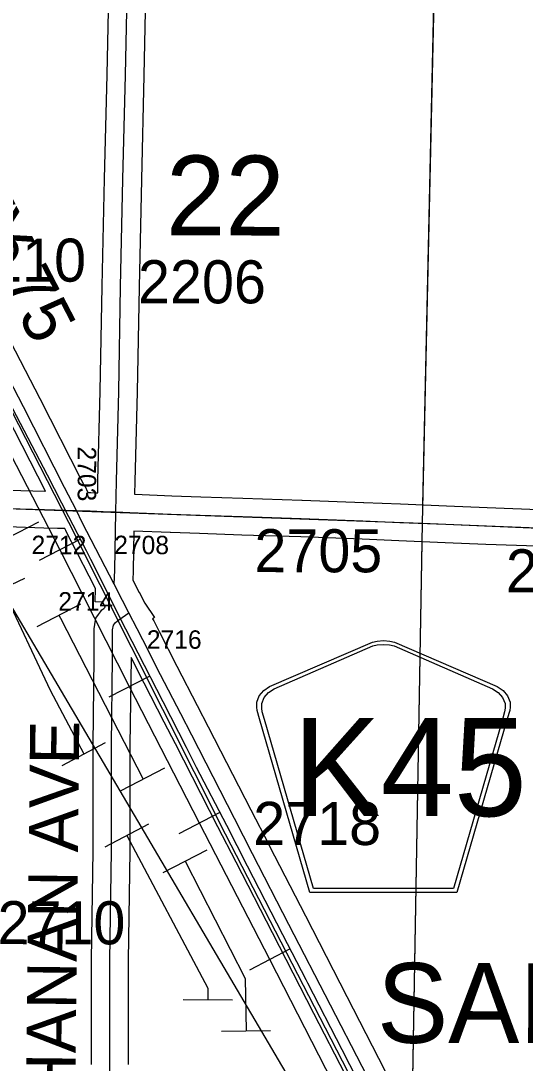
# Model space of a CAD drawing. Extents: x -157.2 to -99.3, y 12.2 to 46.2.
# Drawn here: x -143.504 to -142.682, y 24.227 to 25.924 of the extents above; entities that cross this region are included whole.
import ezdxf

# ---------------------------------------------------------------- set-up
doc = ezdxf.new("R2010")
doc.units = 0
for name, color, linetype in [('tdCoCorpTxt', 7, 'Continuous'), ('tdCoPipe', 7, 'Continuous'), ('tdCoPipe1', 7, 'Continuous'), ('tdCoPipe2', 7, 'Continuous'), ('tdCoRRCL', 7, 'Continuous'), ('tdCoSecRdNmbr', 7, 'Continuous'), ('tdCoSecRdTxt', 7, 'Continuous'), ('tdCoSecRteBand', 7, 'Continuous'), ('tdCoSecRteCL', 7, 'Continuous'), ('tdCoSectLine', 7, 'Continuous'), ('tdCoSectLinePart', 7, 'Continuous'), ('tdCoSectNmbr', 7, 'Continuous'), ('tdCoShieldCoRteHrd', 7, 'Continuous'), ('tdCoSurfAsphalt', 7, 'Continuous'), ('tdCoSurfConc', 7, 'Continuous'), ('tdCoSurfEarth', 7, 'Continuous'), ('tdCoSurfGravel', 7, 'Continuous')]:
    doc.layers.add(name, color=color, linetype=linetype)

msp = doc.modelspace()

# ---------------------------------------------------------------- linework, layer by layer
at = {"layer": 'tdCoPipe'}
msp.add_lwpolyline([(-144.5317, 38.1832), (-143.5928, 36.8918), (-143.6099, 34.8602), (-143.4402, 34.5415), (-143.5694, 34.3304), (-143.5634, 33.7239), (-143.4667, 33.4993), (-143.5656, 33.4168), (-143.4755, 33.1706), (-143.455, 32.2186), (-143.5122, 31.3968), (-143.6938, 30.9939), (-143.6811, 29.9265), (-143.7347, 27.6406), (-143.7362, 26.8708), (-143.9217, 26.7732), (-143.8183, 26.5085), (-143.8116, 26.1034), (-144.0839, 25.9289), (-143.0557, 24.1836)], dxfattribs=at)
at = {"layer": 'tdCoPipe1'}
for p, q in [((-143.5457, 25.0716), (-143.4743, 25.1082)), ((-143.4772, 24.9381), (-143.4059, 24.9747)), ((-143.3403, 24.6712), (-143.269, 24.7078)), ((-143.2718, 24.5377), (-143.2005, 24.5743)), ((-143.1771, 24.2791), (-143.0969, 24.2802))]:
    msp.add_line(p, q, dxfattribs=at)
for points in [[(-143.4415, 24.9564), (-143.439, 24.9515), (-143.3046, 24.6895)], [(-143.2362, 24.556), (-143.1381, 24.3649), (-143.137, 24.2797)]]:
    msp.add_lwpolyline(points, dxfattribs=at)
at = {"layer": 'tdCoPipe2'}
for p, q in [((-143.5698, 24.9824), (-143.4973, 25.0166)), ((-143.4363, 24.7118), (-143.3655, 24.7493)), ((-143.3662, 24.5792), (-143.2953, 24.6167)), ((-143.2393, 24.3307), (-143.1592, 24.3304))]:
    msp.add_line(p, q, dxfattribs=at)
for points in [[(-143.5336, 24.9995), (-143.4557, 24.8341), (-143.4009, 24.7305)], [(-143.3308, 24.5979), (-143.1992, 24.3491), (-143.1992, 24.3306)]]:
    msp.add_lwpolyline(points, dxfattribs=at)
at = {"layer": 'tdCoRRCL'}
for p, q in [((-143.4073, 25.0797), (-143.4739, 25.0452)), ((-143.2936, 24.8571), (-143.3604, 24.823)), ((-143.1797, 24.6354), (-143.2462, 24.6007)), ((-143.0649, 24.4131), (-143.1315, 24.3786))]:
    msp.add_line(p, q, dxfattribs=at)
for points in [[(-142.7262, 23.739), (-143.1704, 24.6), (-143.4255, 25.1074), (-144.37, 26.9512), (-144.9761, 28.127), (-145.218, 28.6071), (-145.4618, 29.0746), (-145.6726, 29.4889)], [(-142.984, 24.1736), (-143.0984, 24.3958), (-143.2126, 24.6181), (-143.3271, 24.8407), (-143.4403, 25.0634), (-143.5554, 25.2851), (-143.6701, 25.5081), (-143.7843, 25.7301), (-143.8986, 25.9522), (-144.0122, 26.1747), (-144.1269, 26.3975), (-144.241, 26.6197), (-144.3551, 26.8418), (-144.4697, 27.0637), (-144.5841, 27.286), (-144.6989, 27.509), (-144.8132, 27.7309), (-144.9272, 27.9528), (-145.0424, 28.1754), (-145.1566, 28.3975), (-145.2703, 28.62), (-145.3849, 28.8426), (-145.4992, 29.0643), (-145.6132, 29.2868)], [(-142.9429, 24.1755), (-142.9806, 24.2489), (-143.0365, 24.3577), (-143.039, 24.3626), (-143.0771, 24.4361), (-143.1345, 24.548), (-143.1683, 24.6141), (-143.2176, 24.7085), (-143.2338, 24.741), (-143.2719, 24.8152), (-143.3327, 24.9339), (-143.3898, 25.047), (-143.3969, 25.061), (-143.4255, 25.1164), (-143.4603, 25.1843), (-143.5233, 25.3046), (-143.5662, 25.3882), (-143.6239, 25.4996), (-143.6467, 25.5451), (-143.6653, 25.5824), (-143.7209, 25.6883), (-143.7702, 25.7851), (-143.8195, 25.8805), (-143.8562, 25.9518)]]:
    msp.add_lwpolyline(points, dxfattribs=at)
at = {"layer": 'tdCoSecRteBand'}
for points in [[(-143.3784, 25.1556), (-143.378, 25.1752), (-143.378, 25.1753), (-143.378, 25.1754), (-143.3743, 25.3213), (-143.3711, 25.4916), (-143.3711, 25.4916), (-143.3711, 25.4917), (-143.3674, 25.6668), (-143.3674, 25.6668), (-143.3674, 25.6669), (-143.3632, 25.8362), (-143.3593, 26.0194)], [(-143.2993, 26.0181), (-143.3032, 25.8349), (-143.3032, 25.8348), (-143.3032, 25.8348), (-143.3074, 25.6654), (-143.3111, 25.4904), (-143.3143, 25.3201), (-143.3143, 25.32), (-143.3143, 25.3199), (-143.318, 25.174), (-143.3184, 25.1533), (-143.3179, 25.1533), (-143.3179, 25.1533), (-143.2579, 25.1508), (-143.2105, 25.1491), (-143.142, 25.1469), (-143.0461, 25.1439), (-143.0459, 25.1439), (-143.0458, 25.1439), (-142.9455, 25.14), (-142.9454, 25.14), (-142.9454, 25.14), (-142.8855, 25.1375), (-142.8854, 25.1375), (-142.8854, 25.1375), (-142.8105, 25.1343), (-142.7442, 25.1316), (-142.6609, 25.1284)], [(-143.5609, 25.4789), (-143.4729, 25.3091), (-143.4728, 25.309), (-143.4728, 25.3089), (-143.406, 25.1778), (-143.4002, 25.1666), (-143.3996, 25.1669), (-143.3943, 25.1562), (-143.3899, 25.156), (-143.3897, 25.156), (-143.3897, 25.156), (-143.3823, 25.1558), (-143.3823, 25.1557), (-143.3784, 25.1556)], [(-143.4634, 25.1582), (-143.5262, 25.2815)], [(-143.5234, 25.16), (-143.4644, 25.1582), (-143.4644, 25.1582), (-143.4643, 25.1582), (-143.4634, 25.1582)], [(-143.3888, 24.2252), (-143.3886, 24.3952), (-143.3886, 24.3953), (-143.3886, 24.3955), (-143.3861, 24.5729), (-143.3859, 24.7449), (-143.3859, 24.745), (-143.3859, 24.7452), (-143.3841, 24.887), (-143.3841, 24.9325), (-143.3841, 24.935), (-143.3837, 24.9374), (-143.3825, 24.9448), (-143.3813, 24.9517), (-143.3772, 24.9574), (-143.374, 24.9619), (-143.3717, 24.9651), (-143.3687, 24.9675), (-143.3662, 24.9696), (-143.3703, 24.9775), (-143.3828, 24.978), (-143.3819, 25.0001), (-143.3921, 25.0197), (-143.4302, 25.0936), (-143.4304, 25.0938), (-143.4305, 25.094), (-143.4321, 25.0973), (-143.4441, 25.0976), (-143.4661, 25.0983), (-143.5253, 25.1)], [(-142.6633, 25.0685), (-142.7466, 25.0717), (-142.7466, 25.0717), (-142.7466, 25.0717), (-142.813, 25.0744), (-142.813, 25.0744), (-142.813, 25.0744), (-142.888, 25.0776), (-142.9478, 25.08), (-143.048, 25.084), (-143.1439, 25.0869), (-143.1439, 25.0869), (-143.1439, 25.0869), (-143.2125, 25.0892), (-143.2125, 25.0892), (-143.2126, 25.0892), (-143.2602, 25.0909), (-143.2602, 25.0909), (-143.2603, 25.0909), (-143.3195, 25.0933), (-143.3207, 25.0291), (-143.3207, 25.0287), (-143.3207, 25.0284), (-143.3213, 25.0135), (-143.3147, 25.0007), (-143.3147, 25.0007), (-143.3113, 24.994), (-143.3112, 24.9939), (-143.3019, 24.9758), (-143.2859, 24.9528), (-143.289, 24.9507), (-143.2873, 24.9473), (-143.2784, 24.9298), (-143.2494, 24.8732), (-143.2166, 24.8096), (-143.2166, 24.8096), (-143.2166, 24.8096), (-143.1986, 24.7746), (-143.1986, 24.7746), (-143.1986, 24.7745), (-143.1293, 24.6394), (-143.0995, 24.5818), (-143.0995, 24.5818), (-143.0995, 24.5817), (-143.0403, 24.4668), (-143.0403, 24.4668), (-143.0403, 24.4668), (-142.973, 24.3355), (-142.9214, 24.2356), (-142.9214, 24.2356), (-142.9214, 24.2356), (-142.8995, 24.1929)], [(-142.9748, 24.2081), (-143.0263, 24.308), (-143.0263, 24.308), (-143.0263, 24.308), (-143.0937, 24.4394), (-143.1528, 24.5542), (-143.1826, 24.6119), (-143.1827, 24.612), (-143.1827, 24.612), (-143.252, 24.7472), (-143.27, 24.7821), (-143.3028, 24.8458), (-143.3028, 24.8458), (-143.3028, 24.8458), (-143.3241, 24.8876), (-143.3241, 24.8869), (-143.3241, 24.8867), (-143.3241, 24.8865), (-143.3259, 24.7446), (-143.3261, 24.5726), (-143.3261, 24.5724), (-143.3261, 24.5723), (-143.3286, 24.3949), (-143.3288, 24.2249)]]:
    msp.add_lwpolyline(points, dxfattribs=at)
at = {"layer": 'tdCoSecRteCL'}
for points in [[(-143.349, 25.1244), (-143.348, 25.1746), (-143.3443, 25.3206), (-143.3411, 25.491), (-143.3374, 25.6661), (-143.3332, 25.8355), (-143.3293, 26.0188), (-143.3269, 26.1241)], [(-143.4132, 25.1267), (-143.4327, 25.1641), (-143.4995, 25.2953), (-143.5876, 25.4652), (-143.6455, 25.5779), (-143.6776, 25.6403), (-143.7444, 25.7702), (-143.808, 25.8925), (-143.8205, 25.917)], [(-143.8493, 25.1417), (-143.8221, 25.1408), (-143.8164, 25.1406), (-143.7407, 25.1379), (-143.6684, 25.1352), (-143.5868, 25.1325), (-143.5244, 25.13), (-143.4652, 25.1283), (-143.4132, 25.1267)], [(-143.3516, 25.0068), (-143.4036, 25.1073), (-143.4132, 25.1267)], [(-143.4132, 25.1267), (-143.3908, 25.126), (-143.3587, 25.1248), (-143.349, 25.1244)], [(-143.3516, 25.0068), (-143.3507, 25.0296), (-143.349, 25.1244)], [(-143.349, 25.1244), (-143.3264, 25.1236), (-143.2591, 25.1209), (-143.2115, 25.1191), (-143.1429, 25.1169), (-143.047, 25.114), (-142.9466, 25.11), (-142.8867, 25.1075), (-142.8117, 25.1043), (-142.7454, 25.1016), (-142.662, 25.0984), (-142.576, 25.0945), (-142.4579, 25.0893), (-142.3728, 25.0851), (-142.3539, 25.0841)], [(-143.3277, 24.9603), (-143.338, 24.9803), (-143.3516, 25.0068)], [(-143.3676, 23.6276), (-143.3667, 23.7285), (-143.3657, 23.7759), (-143.3643, 23.9056), (-143.361, 24.058), (-143.3588, 24.225), (-143.3586, 24.3951), (-143.3561, 24.5727), (-143.3559, 24.7448), (-143.3541, 24.8869), (-143.3541, 24.9325), (-143.3529, 24.9399), (-143.3497, 24.9443), (-143.3443, 24.9488), (-143.3277, 24.9603)], [(-142.8896, 24.1076), (-142.9261, 24.1792), (-142.9481, 24.2219), (-142.9996, 24.3217), (-143.067, 24.4531), (-143.1262, 24.568), (-143.156, 24.6257), (-143.2253, 24.7609), (-143.2433, 24.7959), (-143.2761, 24.8595), (-143.3051, 24.9161), (-143.3143, 24.9342), (-143.3277, 24.9603)]]:
    msp.add_lwpolyline(points, dxfattribs=at)
at = {"layer": 'tdCoSectLine'}
for points in [[(-142.8498, 25.106), (-142.8275, 26.1035)], [(-143.8497, 25.1417), (-142.8498, 25.106)], [(-142.8668, 24.1102), (-142.8498, 25.106)], [(-142.8498, 25.106), (-141.852, 25.0633)]]:
    msp.add_lwpolyline(points, dxfattribs=at)
at = {"layer": 'tdCoSectLinePart'}
for points in [[(-142.8491, 25.1359), (-142.8282, 26.0741)], [(-142.8663, 24.1401), (-142.8503, 25.076)]]:
    msp.add_lwpolyline(points, dxfattribs=at)
at = {"layer": 'tdCoShieldCoRteHrd'}
for points in [[(-143.033, 24.505), (-143.115, 24.7879), (-143.1188, 24.8011), (-143.1196, 24.8069), (-143.1196, 24.8148), (-143.1153, 24.8251), (-143.1081, 24.8336), (-143.0985, 24.8402), (-142.9312, 24.9126), (-142.9237, 24.9142), (-142.9133, 24.9151), (-142.9028, 24.9142), (-142.8953, 24.9126), (-142.728, 24.8402), (-142.7185, 24.8336), (-142.7112, 24.8251), (-142.707, 24.8148), (-142.707, 24.8069), (-142.7077, 24.8011), (-142.7116, 24.7879), (-142.7935, 24.505)], [(-143.0272, 24.5113), (-143.1069, 24.7866), (-143.1106, 24.7992), (-143.1113, 24.8049), (-143.1113, 24.8124), (-143.1072, 24.8223), (-143.1003, 24.8304), (-143.0911, 24.8368), (-142.9305, 24.9063), (-142.9233, 24.9079), (-142.9133, 24.9087), (-142.9033, 24.9079), (-142.896, 24.9063), (-142.7355, 24.8368), (-142.7263, 24.8304), (-142.7193, 24.8223), (-142.7152, 24.8124), (-142.7152, 24.8049), (-142.7159, 24.7992), (-142.7196, 24.7866), (-142.7994, 24.5113)]]:
    msp.add_lwpolyline(points, close=True, dxfattribs=at)
at = {"layer": 'tdCoSurfAsphalt'}
for points in [[(-143.3051, 24.9161), (-143.3143, 24.9342), (-143.3277, 24.9603), (-143.338, 24.9803), (-143.3516, 25.0068), (-143.4036, 25.1073), (-143.4132, 25.1267), (-143.4327, 25.1641), (-143.4995, 25.2953), (-143.5876, 25.4652), (-143.6455, 25.5779), (-143.6776, 25.6403), (-143.7444, 25.7702), (-143.808, 25.8925), (-143.8205, 25.917), (-143.8346, 25.9446)], [(-142.8896, 24.1076), (-142.9261, 24.1792), (-142.9481, 24.2219), (-142.9996, 24.3217), (-143.067, 24.4531), (-143.1262, 24.568), (-143.156, 24.6257), (-143.2253, 24.7609), (-143.2433, 24.7959), (-143.2761, 24.8595), (-143.3051, 24.9161)]]:
    msp.add_lwpolyline(points, dxfattribs=at)
at = {"layer": 'tdCoSurfConc'}
msp.add_lwpolyline([(-144.4941, 25.1459), (-144.3873, 25.1424), (-144.154, 25.1349), (-144.1023, 25.1329), (-144.0797, 25.1322), (-144.0554, 25.132), (-144.024, 25.134), (-144.0014, 25.1358), (-143.9528, 25.1408), (-143.9397, 25.142), (-143.9258, 25.1426), (-143.8986, 25.1431), (-143.8761, 25.1426), (-143.856, 25.1419), (-143.8493, 25.1417), (-143.8221, 25.1408), (-143.8164, 25.1406), (-143.7407, 25.1379), (-143.6684, 25.1352), (-143.5868, 25.1325), (-143.5244, 25.13), (-143.4652, 25.1283), (-143.4132, 25.1267)], dxfattribs=at)
at = {"layer": 'tdCoSurfEarth'}
msp.add_lwpolyline([(-143.3676, 23.6276), (-143.3667, 23.7285), (-143.3657, 23.7759), (-143.3643, 23.9056), (-143.361, 24.058), (-143.3588, 24.225), (-143.3586, 24.3951), (-143.3561, 24.5727), (-143.3559, 24.7448), (-143.3541, 24.8869), (-143.3541, 24.9325), (-143.3529, 24.9399), (-143.3497, 24.9443), (-143.3443, 24.9488), (-143.3277, 24.9603)], dxfattribs=at)
at = {"layer": 'tdCoSurfGravel'}
for points in [[(-143.349, 25.1244), (-143.348, 25.1746), (-143.3443, 25.3206), (-143.3411, 25.491), (-143.3374, 25.6661), (-143.3332, 25.8355), (-143.3293, 26.0188), (-143.3269, 26.1241), (-143.3251, 26.202), (-143.3216, 26.3739), (-143.3182, 26.5401), (-143.315, 26.6834), (-143.312, 26.8496), (-143.309, 27.0239), (-143.3072, 27.1221)], [(-143.4132, 25.1267), (-143.3908, 25.126), (-143.3587, 25.1248), (-143.349, 25.1244), (-143.3264, 25.1236), (-143.2591, 25.1209), (-143.2115, 25.1191), (-143.1429, 25.1169), (-143.047, 25.114), (-142.9466, 25.11), (-142.8867, 25.1075), (-142.8117, 25.1043), (-142.7454, 25.1016), (-142.662, 25.0984), (-142.576, 25.0945), (-142.4579, 25.0893), (-142.3728, 25.0851), (-142.3539, 25.0841), (-141.8584, 25.0635), (-141.788, 25.0608), (-141.4583, 25.0468), (-141.1121, 25.0332), (-140.8461, 25.0216)], [(-143.3516, 25.0068), (-143.3507, 25.0296), (-143.349, 25.1244)]]:
    msp.add_lwpolyline(points, dxfattribs=at)

# ---------------------------------------------------------------- texts
at = {"layer": 'tdCoCorpTxt'}
msp.add_text('SALIX', height=0.13, rotation=359.891, dxfattribs=at).set_placement((-142.9238, 24.2604))
at = {"layer": 'tdCoSecRdNmbr'}
for s, height, rotation, p in [('2210', 0.07, 359.8904, (-143.6057, 25.4997)), ('2206', 0.07, 359.8906, (-143.3129, 25.4643)), ('2703', 0.03, 269.8945, (-143.4109, 25.231)), ('2705', 0.07, 359.8908, (-143.1234, 25.0265)), ('2712', 0.03, 359.8945, (-143.4862, 25.0558)), ('2708', 0.03, 359.8945, (-143.3516, 25.0558)), ('2601', 0.07, 359.8911, (-142.7139, 24.9937)), ('2714', 0.03, 359.8945, (-143.4426, 24.964)), ('2716', 0.03, 359.8945, (-143.2985, 24.9019)), ('2718', 0.07, 359.8908, (-143.1253, 24.5826)), ('2710', 0.07, 359.8904, (-143.5417, 24.421))]:
    msp.add_text(s, height=height, rotation=rotation, dxfattribs=at).set_placement(p)
at = {"layer": 'tdCoSecRdTxt'}
for s, rotation, p in [('OLD HWY 75', 297.3738, (-143.7797, 25.9682)), ('BUCHANAN AVE', 89.3676, (-143.4177, 23.9402))]:
    msp.add_text(s, height=0.08, rotation=rotation, dxfattribs=at).set_placement(p)
at = {"layer": 'tdCoSectNmbr'}
msp.add_text('22', height=0.13, rotation=359.8906, dxfattribs=at).set_placement((-143.2674, 25.5747))
at = {"layer": 'tdCoShieldCoRteHrd'}
msp.add_text('K45', height=0.16, dxfattribs=at).set_placement((-143.0604, 24.6293))

doc.saveas('drawing.dxf')
